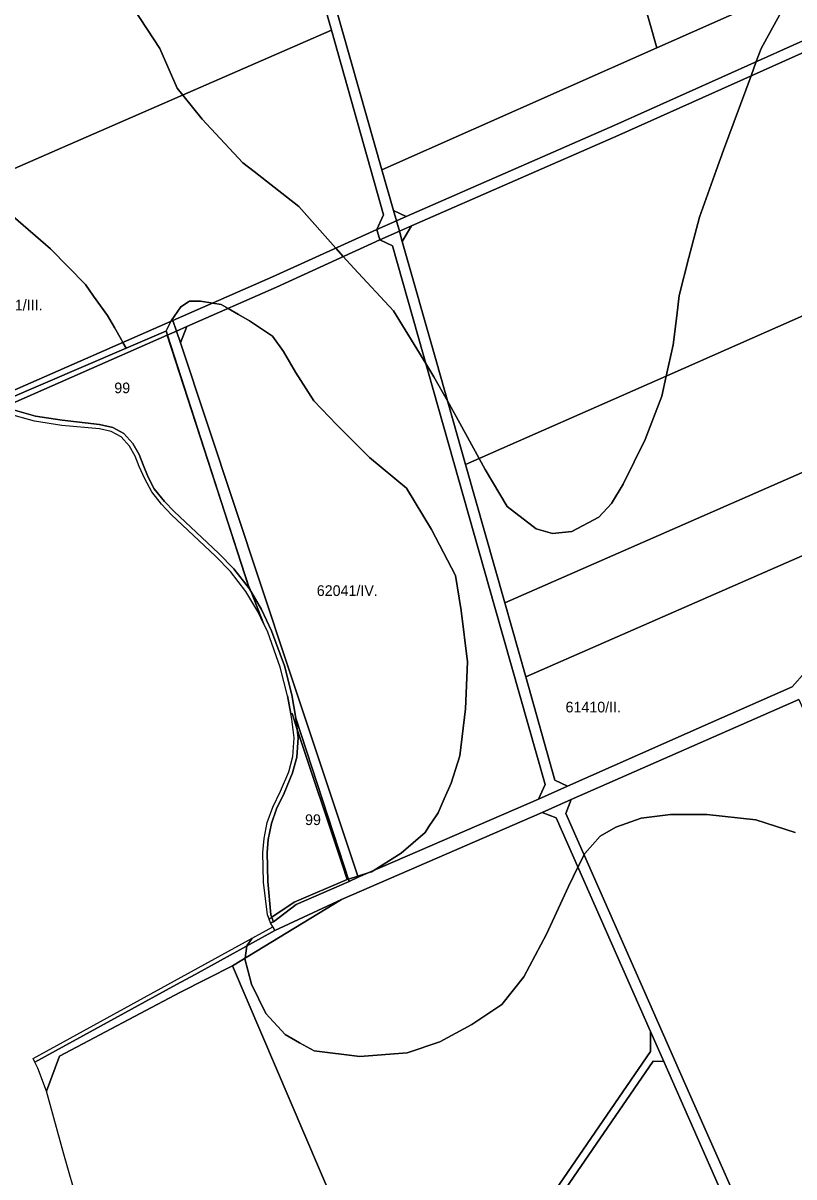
# Model space of a CAD drawing. Extents: x -522079 to -518833, y -1142400 to -1139961.
# Drawn here: x -521253 to -520891, y -1142050 to -1141508 of the extents above; entities that cross this region are included whole.
import ezdxf

# ---------------------------------------------------------------- set-up
doc = ezdxf.new("R2010")
doc.units = 0
for name, color, linetype in [('95560013', 7, 'Continuous'), ('95620013', 7, 'Continuous'), ('95630013', 7, 'Continuous'), ('95640013', 7, 'Continuous'), ('95660013', 7, 'Continuous')]:
    doc.layers.add(name, color=color, linetype=linetype)

msp = doc.modelspace()

# ---------------------------------------------------------------- linework, layer by layer
at = {"layer": '95560013'}
for points in [[(-520980.65, -1141429.68), (-520851.22, -1141372.34), (-520845.27, -1141393.64), (-520844.73, -1141395.54), (-520826.14, -1141462.3), (-520955.18, -1141519.6)], [(-521378.39, -1141629.5), (-521389.3, -1141621.72), (-521393.54, -1141617.98), (-521399.61, -1141612.42), (-521404.05, -1141606.86), (-521406.05, -1141602.85), (-521409.49, -1141593.05), (-521412.01, -1141585.06), (-521414.13, -1141574.69), (-521415.34, -1141566.3), (-521417.47, -1141538.2), (-521418.07, -1141529.55), (-521421, -1141521.26), (-521425.07, -1141514.17), (-521310.56, -1141462.49), (-521142.48, -1141389.44), (-521107.96, -1141511.35), (-521234.07, -1141566.44)], [(-520980.65, -1141429.68), (-520955.18, -1141519.6), (-521084.21, -1141576.91), (-521109.72, -1141486.85)], [(-520821.3, -1141482.16), (-520824.28, -1141488.21), (-520974.97, -1141555.99), (-521072.78, -1141598.79), (-521078.78, -1141596.05), (-521084.21, -1141576.91), (-520955.18, -1141519.6), (-520826.14, -1141462.3)], [(-520819.82, -1141495.44), (-520822.47, -1141493.04), (-520972.97, -1141560.63), (-521070.28, -1141603.2), (-521076.03, -1141605.72), (-521077.42, -1141600.82), (-521072.78, -1141598.79), (-520974.97, -1141555.99), (-520824.28, -1141488.21), (-520821.3, -1141482.16)], [(-520822.47, -1141493.04), (-520819.82, -1141495.44), (-520847.36, -1141628.04), (-520954.68, -1141675.43), (-521044.98, -1141715.3), (-521058.67, -1141667), (-521074.66, -1141610.52), (-521070.28, -1141603.2), (-520972.97, -1141560.63)], [(-521257.85, -1141680.84), (-521266.74, -1141680.79), (-521277.4, -1141677.06), (-521313.67, -1141663.71), (-521328.02, -1141658.46), (-521341.44, -1141652.02), (-521378.39, -1141629.5), (-521234.07, -1141566.44), (-521107.96, -1141511.35), (-521083.41, -1141598.05), (-521086.66, -1141604.9), (-521135.66, -1141627.18), (-521182.3, -1141647.66)], [(-521078.78, -1141596.05), (-521072.78, -1141598.79), (-521077.42, -1141600.82)], [(-521085.26, -1141609.76), (-521133.64, -1141631.93), (-521175.81, -1141650.49), (-521180.65, -1141652.62), (-521182.3, -1141647.66), (-521135.66, -1141627.18), (-521086.66, -1141604.9)], [(-521076.03, -1141605.72), (-521070.28, -1141603.2), (-521074.66, -1141610.52)], [(-521095.32, -1141908.99), (-521128.33, -1141809.83), (-521178.83, -1141658.1), (-521175.81, -1141650.49), (-521133.64, -1141631.93), (-521085.26, -1141609.76), (-521079.3, -1141612.54), (-521031.39, -1141781.75), (-521007.67, -1141865.49), (-521010.77, -1141872.32)], [(-521044.98, -1141715.3), (-520954.68, -1141675.43), (-520847.36, -1141628.04), (-520854, -1141657.98), (-520864.49, -1141709.14), (-521026.62, -1141780.12)], [(-521180.65, -1141652.62), (-521175.81, -1141650.49), (-521178.83, -1141658.1)], [(-521026.62, -1141780.12), (-520864.49, -1141709.14), (-520873.01, -1141751.95), (-521016.76, -1141814.92)], [(-520873.01, -1141751.95), (-520885.53, -1141812.75), (-520891.63, -1141819.53), (-520930.02, -1141836.55), (-520997.06, -1141866.15), (-521003.04, -1141863.38), (-521016.76, -1141814.92)], [(-520997.93, -1141879.1), (-520995.39, -1141872.52), (-520888.63, -1141825.55), (-520837.29, -1141940.33), (-520792.44, -1142040.74), (-520794.02, -1142043.2), (-520832.63, -1142100.89), (-520865.14, -1142158.06), (-520874.16, -1142159.29), (-520905.36, -1142088.65), (-520939.85, -1142010.61), (-520967.25, -1141948.55)], [(-521068.69, -1142151.23), (-521113.51, -1142046.12), (-521154.29, -1141950.51), (-521103.17, -1141919.44), (-521009, -1141878.54), (-521002.46, -1141881.16), (-520958.2, -1141981.43), (-520958.22, -1141990.78), (-521045.32, -1142117.79)], [(-521235.48, -1141993.03), (-521178.81, -1141962.98), (-521154.29, -1141950.51), (-521113.51, -1142046.12), (-521068.69, -1142151.23), (-521143.48, -1142258.25), (-521148.58, -1142258.19), (-521154.1, -1142249.25), (-521169.79, -1142225.11), (-521174.19, -1142217.64), (-521189.97, -1142191.57), (-521192.34, -1142183.35), (-521198.94, -1142162.11), (-521208.63, -1142126.99), (-521218.49, -1142092.03), (-521226.84, -1142062.52), (-521233.47, -1142038.91), (-521241.65, -1142009.35)], [(-520951.97, -1141995.53), (-520956.88, -1141995.37), (-521042.42, -1142119.65), (-521141.2, -1142261.95), (-521141.26, -1142270.03), (-521148.58, -1142258.19), (-521143.48, -1142258.25), (-521068.69, -1142151.23), (-521045.32, -1142117.79), (-520958.22, -1141990.78), (-520958.2, -1141981.43)], [(-521011.25, -1142185.11), (-521102.18, -1142315.9), (-521121.26, -1142296.3), (-521140.11, -1142271.9), (-521141.26, -1142270.03), (-521141.2, -1142261.95), (-521042.42, -1142119.65), (-520956.88, -1141995.37), (-520951.97, -1141995.53), (-520924.06, -1142058.74)]]:
    msp.add_lwpolyline(points, close=True, dxfattribs=at)
at = {"layer": '95620013'}
for points in [[(-521261.42, -1141688.16), (-521185.06, -1141654.56), (-521146.44, -1141773.64), (-521153.73, -1141764.26), (-521160.88, -1141756.78), (-521181.74, -1141737.31), (-521186.22, -1141732.52), (-521191.06, -1141726.58), (-521193.87, -1141721.1), (-521196.27, -1141715.36), (-521198.1, -1141710.58), (-521201.07, -1141705.38), (-521205.36, -1141700.71), (-521210.58, -1141697.9), (-521216.85, -1141696.44), (-521234.23, -1141694.42), (-521246.75, -1141692.49), (-521258.87, -1141689.08)], [(-521130.11, -1141869.48), (-521126.12, -1141860.01), (-521124.12, -1141852.65), (-521123.46, -1141843.47), (-521124.58, -1141834.32), (-521099.58, -1141911), (-521124.47, -1141921.72), (-521135.11, -1141929.87), (-521136.31, -1141926.58), (-521137.83, -1141911.01), (-521138.09, -1141897.36), (-521137.56, -1141891.19), (-521136.12, -1141883.81), (-521133.7, -1141876.9)]]:
    msp.add_lwpolyline(points, close=True, dxfattribs=at)
at = {"layer": '95630013'}
msp.add_lwpolyline([(-521258.87, -1141689.08), (-521246.75, -1141692.49), (-521234.23, -1141694.42), (-521216.85, -1141696.44), (-521210.58, -1141697.9), (-521205.36, -1141700.71), (-521201.07, -1141705.38), (-521198.1, -1141710.58), (-521196.27, -1141715.36), (-521193.87, -1141721.1), (-521191.06, -1141726.58), (-521186.22, -1141732.52), (-521181.74, -1141737.31), (-521160.88, -1141756.78), (-521153.73, -1141764.26), (-521146.44, -1141773.64), (-521140.73, -1141783.35), (-521136, -1141793.25), (-521130, -1141809.79), (-521126.54, -1141823.43), (-521124.58, -1141834.32), (-521123.46, -1141843.47), (-521124.12, -1141852.65), (-521126.12, -1141860.01), (-521130.11, -1141869.48), (-521133.7, -1141876.9), (-521136.12, -1141883.81), (-521137.56, -1141891.19), (-521138.09, -1141897.36), (-521137.83, -1141911.01), (-521136.31, -1141926.58), (-521135.11, -1141929.87), (-521136.46, -1141930.46), (-521137.86, -1141926.67), (-521139.81, -1141911.29), (-521140.05, -1141897.31), (-521139.56, -1141890.84), (-521138.03, -1141883.29), (-521135.49, -1141876.13), (-521131.82, -1141868.6), (-521127.98, -1141859.55), (-521126.1, -1141852.28), (-521125.45, -1141843.51), (-521126.47, -1141834.73), (-521128.54, -1141823.8), (-521131.96, -1141810.32), (-521137.85, -1141793.99), (-521142.46, -1141784.23), (-521148.13, -1141774.78), (-521155.26, -1141765.5), (-521162.29, -1141758.22), (-521183.03, -1141738.83), (-521187.74, -1141733.86), (-521192.28, -1141728.07), (-521195.55, -1141722.03), (-521198.13, -1141716.1), (-521199.97, -1141711.28), (-521202.67, -1141706.57), (-521206.66, -1141702.29), (-521211.3, -1141699.75), (-521216.85, -1141698.47), (-521234.47, -1141696.96), (-521247.24, -1141694.95), (-521259.69, -1141691.44)], dxfattribs=at)
msp.add_lwpolyline([(-521103.17, -1141919.44), (-521154.29, -1141950.51), (-521178.81, -1141962.98), (-521235.48, -1141993.03), (-521241.65, -1142009.35), (-521245.74, -1141998.54), (-521247.07, -1141995.86), (-521180.62, -1141959.39), (-521171.94, -1141954.7), (-521134.44, -1141933.97)], close=True, dxfattribs=at)
at = {"layer": '95640013'}
for points in [[(-521147.68, -1141344.03), (-521149.23, -1141347.36), (-521109.72, -1141486.85), (-521084.21, -1141576.91), (-521078.78, -1141596.05), (-521077.42, -1141600.82), (-521086.66, -1141604.9), (-521083.41, -1141598.05), (-521107.96, -1141511.35), (-521142.48, -1141389.44), (-521153.82, -1141349.39), (-521156.76, -1141348.04), (-521157.35, -1141345.97), (-521146.08, -1141340.6)], [(-521077.42, -1141600.82), (-521076.03, -1141605.72), (-521085.26, -1141609.76), (-521086.66, -1141604.9)], [(-521079.3, -1141612.54), (-521085.26, -1141609.76), (-521076.03, -1141605.72), (-521074.66, -1141610.52), (-521058.67, -1141667), (-521044.98, -1141715.3), (-521026.62, -1141780.12), (-521016.76, -1141814.92), (-521003.04, -1141863.38), (-520997.06, -1141866.15), (-521010.77, -1141872.32), (-521007.67, -1141865.49), (-521031.39, -1141781.75)], [(-521257.85, -1141680.84), (-521182.3, -1141647.66), (-521180.65, -1141652.62), (-521185.06, -1141654.56), (-521261.42, -1141688.16), (-521266.74, -1141680.79)], [(-521185.06, -1141654.56), (-521180.65, -1141652.62), (-521178.83, -1141658.1), (-521128.33, -1141809.83), (-521095.32, -1141908.99), (-521099.58, -1141911), (-521124.58, -1141834.32), (-521126.54, -1141823.43), (-521130, -1141809.79), (-521136, -1141793.25), (-521140.73, -1141783.35), (-521146.44, -1141773.64)], [(-521009, -1141878.54), (-520995.39, -1141872.52), (-520997.93, -1141879.1), (-520967.25, -1141948.55), (-520939.85, -1142010.61), (-520905.36, -1142088.65), (-520874.16, -1142159.29), (-520870.13, -1142168.42), (-520873.11, -1142174.16), (-520875.14, -1142169.56), (-520880.4, -1142157.63), (-520924.06, -1142058.74), (-520951.97, -1141995.53), (-520958.2, -1141981.43), (-521002.46, -1141881.16)], [(-521135.45, -1141932.22), (-521134.44, -1141933.97), (-521171.94, -1141954.7), (-521180.62, -1141959.39), (-521247.07, -1141995.86), (-521247.93, -1141994.05), (-521181.6, -1141957.64)]]:
    msp.add_lwpolyline(points, close=True, dxfattribs=at)
msp.add_lwpolyline([(-520888.63, -1141825.55), (-520995.39, -1141872.52), (-521009, -1141878.54), (-521103.17, -1141919.44), (-521134.44, -1141933.97), (-521135.45, -1141932.22), (-521136.46, -1141930.46), (-521135.11, -1141929.87), (-521124.47, -1141921.72), (-521099.58, -1141911), (-521095.32, -1141908.99), (-521010.77, -1141872.32), (-520997.06, -1141866.15), (-520930.02, -1141836.55), (-520891.63, -1141819.53), (-520885.53, -1141812.75)], dxfattribs=at)
at = {"layer": '95660013'}
for points in [[(-520893.11, -1141495.88), (-520906.25, -1141519.97), (-520908.52, -1141526.1), (-520911, -1141532.8), (-520923.92, -1141567.68), (-520927.38, -1141577.27), (-520935.24, -1141599.04), (-520940.16, -1141618.06), (-520944.76, -1141635.85), (-520945.88, -1141645.44), (-520947.47, -1141659.02), (-520950.79, -1141673.71), (-520952.91, -1141683.11), (-520960.61, -1141703.56), (-520971.03, -1141724.46), (-520976.47, -1141733.55), (-520982.36, -1141739.92), (-520995.04, -1141746.73), (-521004.1, -1141747.64), (-521011.8, -1141745.37), (-521025.39, -1141734.92), (-521035.81, -1141717.65), (-521038.6, -1141712.48), (-521047.59, -1141695.84), (-521053.47, -1141685.35), (-521059.82, -1141674.02), (-521063.66, -1141667.79), (-521078.85, -1141643.12), (-521097.42, -1141623.12), (-521102.34, -1141617.59), (-521105.85, -1141613.63), (-521123.24, -1141594.04), (-521144.26, -1141577.68), (-521149.52, -1141573.59), (-521168.54, -1141553.14), (-521177.71, -1141541.82), (-521180.32, -1141538.6), (-521188.48, -1141519.97), (-521200.71, -1141501.34)], [(-521200.71, -1141501.34), (-521188.48, -1141519.97), (-521180.32, -1141538.6), (-521177.71, -1141541.82), (-521168.54, -1141553.14), (-521149.52, -1141573.59), (-521144.26, -1141577.68), (-521123.24, -1141594.04), (-521105.85, -1141613.63), (-521102.34, -1141617.59), (-521097.42, -1141623.12), (-521078.85, -1141643.12), (-521063.66, -1141667.79), (-521059.82, -1141674.02), (-521053.47, -1141685.35), (-521047.59, -1141695.84), (-521038.6, -1141712.48), (-521035.81, -1141717.65), (-521025.39, -1141734.92), (-521011.8, -1141745.37), (-521004.1, -1141747.64), (-520995.04, -1141746.73), (-520982.36, -1141739.92), (-520976.47, -1141733.55), (-520971.03, -1141724.46), (-520960.61, -1141703.56), (-520952.91, -1141683.11), (-520950.79, -1141673.71), (-520947.47, -1141659.02), (-520945.88, -1141645.44), (-520944.76, -1141635.85), (-520940.16, -1141618.06), (-520935.24, -1141599.04), (-520927.38, -1141577.27), (-520923.92, -1141567.68), (-520911, -1141532.8), (-520908.52, -1141526.1), (-520906.25, -1141519.97), (-520893.11, -1141495.88)], [(-521257.35, -1141598.83), (-521239.84, -1141614.01), (-521223.41, -1141630.71), (-521219.52, -1141636.16), (-521213.03, -1141645.24), (-521209.81, -1141650.9), (-521206.47, -1141656.77), (-521206.12, -1141657.38), (-521205.78, -1141657.97), (-521204.3, -1141660.61), (-521262.08, -1141685.51)], [(-520890.31, -1141888.05), (-520908.69, -1141882.05), (-520931.77, -1141879.48), (-520948.87, -1141879.48), (-520962.55, -1141881.19), (-520974.52, -1141885.48), (-520981.78, -1141889.77), (-520989.05, -1141897.91), (-520989.35, -1141898.52), (-520992.24, -1141904.31), (-520994.31, -1141908.48), (-520996.74, -1141913.35), (-521007, -1141935.65), (-521017.69, -1141955.8), (-521027.95, -1141968.67), (-521042.05, -1141978.1), (-521057.01, -1141986.25), (-521072.4, -1141991.39), (-521094.63, -1141993.1), (-521116, -1141990.53), (-521122.84, -1141986.67), (-521129.68, -1141982.82), (-521138.66, -1141972.95), (-521145.49, -1141959.23), (-521147.16, -1141952.56), (-521148.49, -1141947.23), (-521148.45, -1141946.96), (-521147.63, -1141941.24), (-521145.11, -1141937.54), (-521135.45, -1141932.22), (-521136.46, -1141930.46), (-521136.69, -1141929.83), (-521136.78, -1141929.59), (-521137.06, -1141928.83), (-521137.18, -1141928.5), (-521136.24, -1141927.97), (-521135.89, -1141927.73), (-521125.48, -1141920.63), (-521100.56, -1141909.99), (-521099.97, -1141909.81), (-521095.51, -1141908.42), (-521090.17, -1141906.76), (-521089.05, -1141906.41), (-521088.36, -1141905.97), (-521075.24, -1141897.68), (-521063.99, -1141887.94), (-521062.15, -1141885.17), (-521060.15, -1141882.15), (-521058.77, -1141880.08), (-521057.85, -1141878.7), (-521054.99, -1141872.23), (-521051.72, -1141864.85), (-521049.67, -1141858.43), (-521047.62, -1141852.02), (-521045.07, -1141829.96), (-521044.04, -1141807.89), (-521047.11, -1141783.78), (-521049.67, -1141767.36), (-521060.92, -1141745.81), (-521072.69, -1141726.31), (-521090.08, -1141711.94), (-521105.42, -1141696.55), (-521116.16, -1141685.26), (-521124.86, -1141671.92), (-521130.48, -1141662.17), (-521135.6, -1141654.99), (-521146.34, -1141647.81), (-521151.49, -1141644.83), (-521156.44, -1141641.96), (-521159.64, -1141640.11), (-521163.66, -1141639.48), (-521169.36, -1141638.57), (-521174.47, -1141638.57), (-521178.56, -1141641.14), (-521183.17, -1141647.81), (-521183.32, -1141648.1), (-521185.53, -1141652.52), (-521185.64, -1141652.57), (-521204.3, -1141660.61), (-521205.78, -1141657.97), (-521206.12, -1141657.38), (-521206.47, -1141656.77), (-521209.81, -1141650.9), (-521213.03, -1141645.24), (-521219.52, -1141636.16), (-521223.41, -1141630.71), (-521239.84, -1141614.01), (-521257.35, -1141598.83)], [(-521262.08, -1141685.51), (-521204.3, -1141660.61), (-521185.64, -1141652.57), (-521185.53, -1141652.52), (-521184.89, -1141654.49), (-521147.1, -1141771.34), (-521145.67, -1141774.95), (-521139.63, -1141790.22), (-521142.46, -1141784.23), (-521148.13, -1141774.78), (-521155.26, -1141765.5), (-521162.29, -1141758.22), (-521183.03, -1141738.83), (-521187.74, -1141733.86), (-521192.28, -1141728.07), (-521195.55, -1141722.03), (-521198.13, -1141716.1), (-521199.97, -1141711.28), (-521202.67, -1141706.57), (-521206.66, -1141702.29), (-521211.3, -1141699.75), (-521216.85, -1141698.47), (-521234.47, -1141696.96), (-521247.24, -1141694.95), (-521259.69, -1141691.44)], [(-521226.84, -1142062.52), (-521233.47, -1142038.91), (-521241.65, -1142009.35), (-521245.74, -1141998.54), (-521247.07, -1141995.86), (-521247.93, -1141994.05), (-521181.6, -1141957.64), (-521145.11, -1141937.54), (-521147.63, -1141941.24), (-521148.45, -1141946.96), (-521148.49, -1141947.23), (-521147.16, -1141952.56), (-521145.49, -1141959.23), (-521138.66, -1141972.95), (-521129.68, -1141982.82), (-521122.84, -1141986.67), (-521116, -1141990.53), (-521094.63, -1141993.1), (-521072.4, -1141991.39), (-521057.01, -1141986.25), (-521042.05, -1141978.1), (-521027.95, -1141968.67), (-521017.69, -1141955.8), (-521007, -1141935.65), (-520996.74, -1141913.35), (-520994.31, -1141908.48), (-520992.24, -1141904.31), (-520989.35, -1141898.52), (-520989.05, -1141897.91), (-520981.78, -1141889.77), (-520974.52, -1141885.48), (-520962.55, -1141881.19), (-520948.87, -1141879.48), (-520931.77, -1141879.48), (-520908.69, -1141882.05), (-520890.31, -1141888.05)]]:
    msp.add_lwpolyline(points, dxfattribs=at)
for points in [[(-521045.07, -1141829.96), (-521047.62, -1141852.02), (-521049.67, -1141858.43), (-521051.72, -1141864.85), (-521054.99, -1141872.23), (-521057.85, -1141878.7), (-521058.77, -1141880.08), (-521060.15, -1141882.15), (-521062.15, -1141885.17), (-521063.99, -1141887.94), (-521075.24, -1141897.68), (-521088.36, -1141905.97), (-521089.05, -1141906.41), (-521090.17, -1141906.76), (-521095.51, -1141908.42), (-521099.97, -1141909.81), (-521100.56, -1141909.99), (-521102.92, -1141902.87), (-521123.93, -1141839.62), (-521126.43, -1141832.1), (-521126.93, -1141832.29), (-521128.54, -1141823.8), (-521131.96, -1141810.32), (-521137.85, -1141793.99), (-521139.63, -1141790.22), (-521145.67, -1141774.95), (-521147.1, -1141771.34), (-521184.89, -1141654.49), (-521185.53, -1141652.52), (-521183.32, -1141648.1), (-521183.17, -1141647.81), (-521178.56, -1141641.14), (-521174.47, -1141638.57), (-521169.36, -1141638.57), (-521163.66, -1141639.48), (-521159.64, -1141640.11), (-521156.44, -1141641.96), (-521151.49, -1141644.83), (-521146.34, -1141647.81), (-521135.6, -1141654.99), (-521130.48, -1141662.17), (-521124.86, -1141671.92), (-521116.16, -1141685.26), (-521105.42, -1141696.55), (-521090.08, -1141711.94), (-521072.69, -1141726.31), (-521060.92, -1141745.81), (-521049.67, -1141767.36), (-521047.11, -1141783.78), (-521044.04, -1141807.89)], [(-521137.86, -1141926.67), (-521139.81, -1141911.29), (-521140.05, -1141897.31), (-521139.56, -1141890.84), (-521138.03, -1141883.29), (-521135.49, -1141876.13), (-521131.82, -1141868.6), (-521127.98, -1141859.55), (-521126.1, -1141852.28), (-521125.45, -1141843.51), (-521126.47, -1141834.73), (-521128.54, -1141823.8), (-521126.93, -1141832.29), (-521126.43, -1141832.1), (-521123.93, -1141839.62), (-521102.92, -1141902.87), (-521100.56, -1141909.99), (-521125.48, -1141920.63), (-521135.89, -1141927.73), (-521136.24, -1141927.97), (-521137.18, -1141928.5), (-521137.06, -1141928.83)]]:
    msp.add_lwpolyline(points, close=True, dxfattribs=at)

# ---------------------------------------------------------------- texts
for s, p in [('62441/III.', (-521271.4, -1141642.87)), ('99', (-521209.83, -1141681.77)), ('62041/IV.', (-521114.79, -1141776.93)), ('61410/II.', (-520998.04, -1141831.6)), ('99', (-521120.31, -1141884.48))]:
    msp.add_text(s, height=5, rotation=0, dxfattribs=at).set_placement(p)

doc.saveas('drawing.dxf')
